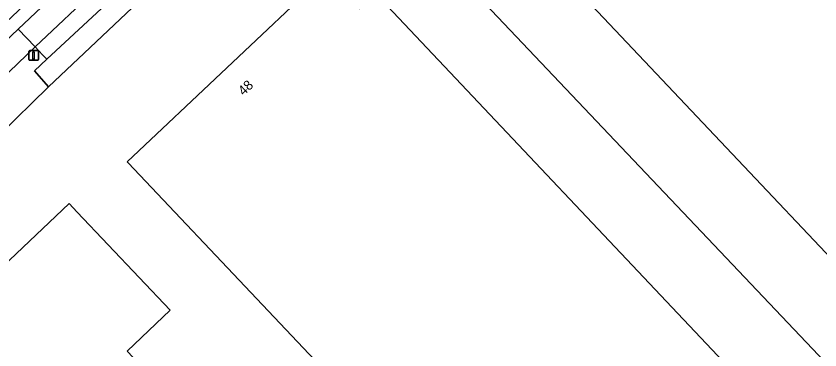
# Model space of a CAD drawing. Extents: x 156702 to 158052, y 387630 to 388992.
# Drawn here: x 157794.6 to 157877.3, y 388423.4 to 388457.8 of the extents above; entities that cross this region are included whole.
import ezdxf

# ---------------------------------------------------------------- set-up
doc = ezdxf.new("R2010")
doc.units = 0
for name, color, linetype in [('IMGEO_Erf', 7, 'Continuous'), ('IMGEO_Groenvoorziening', 7, 'Continuous'), ('IMGEO_Hek', 7, 'Continuous'), ('IMGEO_Lichtmast', 7, 'Continuous'), ('IMGEO_Pand', 7, 'Continuous'), ('IMGEO_Pand_nummerreeks', 7, 'Continuous'), ('IMGEO_Parkeervlak_open', 7, 'Continuous'), ('IMGEO_Rijbaan_lokaal_gesloten', 7, 'Continuous'), ('IMGEO_Voetpad_open', 7, 'Continuous')]:
    doc.layers.add(name, color=color, linetype=linetype)

msp = doc.modelspace()

# ---------------------------------------------------------------- linework, layer by layer
at = {"layer": 'IMGEO_Erf'}
for points in [[(157896.707, 388452.621), (157898.669, 388453.753), (157904.576, 388444.253), (157885.138, 388425.807), (157840.588, 388472.905), (157850.61, 388479.156), (157851.836, 388477.249), (157873.085, 388490.508)], [(157869.733, 388419.752), (157877.259, 388411.776), (157855.125, 388390.856), (157847.584, 388398.828), (157806.093, 388442.689), (157805.996, 388442.792), (157826.505, 388462.157), (157829.914, 388458.53), (157831.595, 388460.131)], [(157828.903, 388399.086), (157819.659, 388390.335), (157810.015, 388381.225), (157800.203, 388391.612), (157786.92, 388405.336), (157787, 388405.411), (157776.631, 388416.385), (157786.895, 388426.115), (157787.273, 388425.716), (157790.124, 388428.402), (157789.758, 388428.796), (157800.014, 388438.514), (157800.858, 388437.621), (157810.402, 388427.538), (157805.987, 388423.319), (157811.695, 388417.284)]]:
    msp.add_lwpolyline(points, close=True, dxfattribs=at)
msp.add_lwpolyline([(157828.567, 388476.717), (157827.02, 388475.574), (157819.744, 388469.314), (157819.109, 388469.983), (157810.78, 388462.732), (157797.894, 388450.521), (157792.808, 388445.559), (157792.292, 388445.075), (157782.368, 388435.768), (157780.291, 388433.819), (157770.375, 388424.519), (157762.137, 388416.71), (157750.411, 388405.749), (157741.215, 388396.791), (157739.918, 388395.57), (157734.391, 388390.366), (157712.553, 388369.817), (157711.355, 388368.682), (157705.627, 388363.261), (157681.507, 388340.173), (157681.329, 388340.003), (157675.827, 388334.804), (157653.403, 388313.608)], dxfattribs=at)
at = {"layer": 'IMGEO_Groenvoorziening'}
msp.add_lwpolyline([(157804.262, 388459.431), (157797.708, 388453.347), (157796.45, 388452.142), (157797.894, 388450.521), (157810.78, 388462.732), (157819.109, 388469.983), (157817.957, 388471.29), (157816.744, 388470.298)], dxfattribs=at)
at = {"layer": 'IMGEO_Hek'}
msp.add_lwpolyline([(157837.15, 388465.089), (157886.097, 388413.502)], dxfattribs=at)
at = {"layer": 'IMGEO_Lichtmast'}
for p, q in [((157795.854, 388453.338), (157795.854, 388454.138)), ((157795.854, 388454.138), (157795.854, 388453.338)), ((157795.954, 388454.238), (157796.744, 388454.238)), ((157796.744, 388454.238), (157795.954, 388454.238)), ((157796.844, 388454.138), (157796.844, 388453.338)), ((157796.844, 388453.338), (157796.844, 388454.138)), ((157796.744, 388453.238), (157795.954, 388453.238)), ((157795.954, 388453.238), (157796.744, 388453.238))]:
    msp.add_line(p, q, dxfattribs=at)
msp.add_lwpolyline([(157796.274, 388454.113), (157796.424, 388454.113), (157796.424, 388453.363), (157796.274, 388453.363), (157796.274, 388454.113)], dxfattribs=at)
for centre, start, end in [((157795.954, 388454.138), 90, 180), ((157795.954, 388454.138), 90, 180), ((157796.744, 388454.138), 0, 90), ((157796.744, 388454.138), 360, 90), ((157795.954, 388453.338), 180, 270), ((157795.954, 388453.338), 180, 270), ((157796.744, 388453.338), 270, 0), ((157796.744, 388453.338), 270, 0)]:
    msp.add_arc(centre, 0.1, start, end, dxfattribs=at)
at = {"layer": 'IMGEO_Pand'}
for points in [[(157873.085, 388490.508), (157851.836, 388477.249), (157850.61, 388479.156), (157840.588, 388472.905), (157885.138, 388425.807), (157904.576, 388444.253), (157898.669, 388453.753), (157896.707, 388452.621)], [(157831.595, 388460.131), (157829.914, 388458.53), (157826.505, 388462.157), (157805.996, 388442.792), (157806.093, 388442.689), (157847.584, 388398.828), (157855.125, 388390.856), (157877.259, 388411.776), (157869.733, 388419.752)], [(157800.858, 388437.621), (157800.014, 388438.514), (157789.758, 388428.796), (157790.124, 388428.402), (157787.273, 388425.716), (157786.895, 388426.115), (157776.631, 388416.385), (157787, 388405.411), (157786.92, 388405.336), (157800.203, 388391.612), (157810.015, 388381.225), (157819.659, 388390.335), (157828.903, 388399.086), (157811.695, 388417.284), (157805.987, 388423.319), (157810.402, 388427.538)]]:
    msp.add_lwpolyline(points, close=True, dxfattribs=at)
at = {"layer": 'IMGEO_Parkeervlak_open'}
msp.add_lwpolyline([(157801.348, 388462.676), (157794.773, 388456.453), (157796.519, 388454.609), (157803.005, 388460.767)], dxfattribs=at)
at = {"layer": 'IMGEO_Rijbaan_lokaal_gesloten'}
msp.add_lwpolyline([(157925.989, 388541.781), (157925.789, 388544.405), (157924.816, 388544.354), (157921.978, 388543.651), (157920.425, 388542.954), (157916.373, 388540.433), (157884.271, 388521.013), (157881.592, 388519.374), (157838.65, 388493.098), (157832.229, 388488.942), (157827.136, 388485.429), (157822.012, 388481.702), (157814.126, 388475.59), (157808.05, 388470.514), (157801.977, 388465.115), (157800.565, 388463.859), (157728.664, 388395.811), (157729.626, 388394.795), (157736.97, 388401.746), (157757.354, 388421.039), (157766.1, 388429.315), (157787.371, 388449.448), (157794.773, 388456.453), (157801.348, 388462.676)], dxfattribs=at)
at = {"layer": 'IMGEO_Voetpad_open'}
msp.add_lwpolyline([(157803.005, 388460.767), (157796.519, 388454.609), (157797.273, 388453.809), (157797.708, 388453.347), (157804.262, 388459.431)], dxfattribs=at)
for points in [[(157796.519, 388454.609), (157794.773, 388456.453), (157787.371, 388449.448), (157789.133, 388447.581), (157789.298, 388447.736)], [(157797.894, 388450.521), (157796.45, 388452.142), (157797.708, 388453.347), (157797.273, 388453.809), (157796.519, 388454.609), (157789.298, 388447.736), (157790.516, 388446.44), (157790.778, 388446.688), (157792.292, 388445.075), (157792.808, 388445.559)]]:
    msp.add_lwpolyline(points, close=True, dxfattribs=at)

# ---------------------------------------------------------------- texts
at = {"layer": 'IMGEO_Pand_nummerreeks'}
msp.add_text('48', height=1, rotation=43.24685, dxfattribs=at).set_placement((157817.978, 388449.547))

doc.saveas('drawing.dxf')
